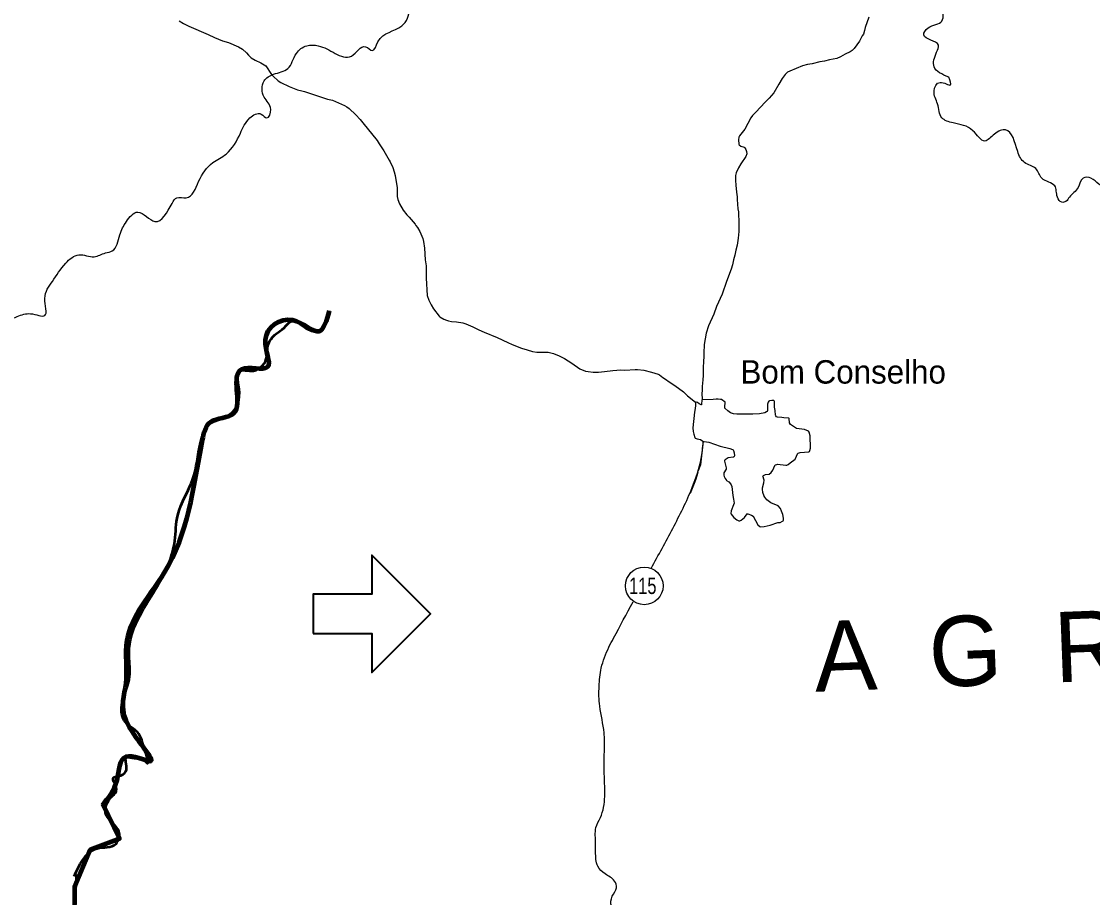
# Model space of a CAD drawing. Extents: x -1643653 to 4543381, y 1624270 to 13878484.
# Drawn here: x 739080 to 761950, y 8976106 to 8994810 of the extents above; entities that cross this region are included whole.
import ezdxf
from ezdxf.enums import TextEntityAlignment as Align

# ---------------------------------------------------------------- set-up
doc = ezdxf.new("R2010")
doc.units = 0
doc.header["$LTSCALE"] = 200
for name, color, linetype, lineweight in [('12', 7, 'Continuous', 25), ('21', 7, 'Continuous', 25), ('24', 7, 'Continuous', 25), ('48', 7, 'Continuous', 25), ('53', 7, 'Continuous', 106), ('60', 7, 'Continuous', 13)]:
    doc.layers.add(name, color=color, linetype=linetype, lineweight=lineweight)
doc.layers.add('41', color=7, linetype='Continuous')
doc.layers.add('55', color=7, linetype='Continuous')

msp = doc.modelspace()

# ---------------------------------------------------------------- linework, layer by layer
at = {"layer": '12'}
for points in [[(757176.2, 8994900.9), (757094.2, 8994681), (757080.3, 8994617.7), (757057.3, 8994539.4), (757030, 8994501.8), (756971.2, 8994387)], [(742450.2, 8994818.9), (742538.4, 8994765.5), (742653.4, 8994708.1), (743063.9, 8994531.9), (743202.8, 8994463.2), (743374.8, 8994394.9), (743503.6, 8994361.7), (743718.4, 8994268.8), (743798, 8994217.1), (743884.6, 8994139.6), (743925.2, 8994087.9), (743987.2, 8994034.5), (744071.1, 8993979.5), (744190.2, 8993923.9), (744295.1, 8993863.4), (744420.2, 8993679.6), (744451.8, 8993640.9), (744562.5, 8993542.9), (744617.5, 8993506.5), (744796.5, 8993422.4), (744976.2, 8993352.4), (745067.8, 8993328), (745127.6, 8993316.5), (745616.2, 8993149), (745683.6, 8993137.9), (745720.2, 8993127.5), (745978.3, 8993014.5), (746031, 8992985.6), (746079.5, 8992950.2), (746223.7, 8992817.6), (746315.6, 8992715.5), (746370.6, 8992646.6)], [(756971.2, 8994387), (756915.9, 8994309.4), (756906.2, 8994289.7), (756893.5, 8994278.5), (756857.7, 8994231), (756816.5, 8994191.4), (756771.9, 8994157.9), (756671.4, 8994111.8), (756570.5, 8994055.5), (756489.1, 8994020.4), (756331.1, 8993988), (756227.8, 8993960.6), (756124.8, 8993944.8), (755962.5, 8993905), (755863.1, 8993888), (755759, 8993864.5), (755485.9, 8993746.7)], [(755485.9, 8993746.7), (755436, 8993725.2), (755388.6, 8993678.9), (755319.8, 8993588), (755254.5, 8993469.5), (755142.1, 8993284), (755043.9, 8993171), (754978.6, 8993106.6), (754841.7, 8992955.8), (754779.1, 8992896.5), (754687.6, 8992799.4), (754651.5, 8992748.6), (754524.1, 8992512.1), (754411.1, 8992365.5), (754398.7, 8992336), (754391.5, 8992281.4), (754397.4, 8992190.1), (754407.1, 8992178.3), (754442.2, 8992150.2), (754510.5, 8992124.1), (754525.7, 8992111.7), (754546.5, 8992078.6), (754558.9, 8992034.2), (754566.8, 8991982.5), (754549.4, 8991924.7), (754437.6, 8991766.5), (754388.2, 8991683.9), (754341.2, 8991577.2), (754329.1, 8991522.1), (754326.6, 8991415.2), (754331, 8991312.1), (754345.5, 8991164.9), (754362.2, 8991061.7), (754363.2, 8991006.3), (754379.5, 8990807.5), (754388.1, 8990748.4), (754401.1, 8990490.5), (754395.5, 8990391.1), (754398.9, 8990324.6), (754386.9, 8990184.8), (754359, 8990030), (754333.6, 8989926.8), (754315.2, 8989820), (754285.7, 8989716.7), (754263.6, 8989613.7), (754232, 8989517.7), (754134.4, 8989256.1), (754043.8, 8988985.6), (753924, 8988727.3), (753924, 8988727.3), (753865.2, 8988561.9), (753752.1, 8988314.6), (753698.9, 8988155), (753660.3, 8987914.5), (753655.8, 8987849.5)], [(755485.9, 8993746.7), (755436, 8993725.2), (755388.6, 8993678.9), (755319.8, 8993588), (755254.5, 8993469.5), (755142.1, 8993284), (755043.9, 8993171), (754978.6, 8993106.6), (754841.7, 8992955.8), (754779.1, 8992896.5), (754687.6, 8992799.4), (754651.5, 8992748.6), (754524.1, 8992512.1), (754411.1, 8992365.5), (754398.7, 8992336), (754391.5, 8992281.4), (754397.4, 8992190.1), (754407.1, 8992178.3), (754442.2, 8992150.2), (754510.5, 8992124.1), (754525.7, 8992111.7), (754546.5, 8992078.6), (754558.9, 8992034.2), (754566.8, 8991982.5), (754549.4, 8991924.7), (754437.6, 8991766.5), (754388.2, 8991683.9), (754341.2, 8991577.2), (754329.1, 8991522.1), (754326.6, 8991415.2), (754331, 8991312.1), (754345.5, 8991164.9), (754362.2, 8991061.7), (754363.2, 8991006.3), (754379.5, 8990807.5), (754388.1, 8990748.4), (754401.1, 8990490.5), (754395.5, 8990391.1), (754398.9, 8990324.6), (754386.9, 8990184.8), (754359, 8990030), (754333.6, 8989926.8), (754315.2, 8989820), (754285.7, 8989716.7), (754263.6, 8989613.7), (754232, 8989517.7), (754134.4, 8989256.1), (754043.8, 8988985.6), (753924, 8988727.3), (753924, 8988727.3), (753865.2, 8988561.9), (753752.1, 8988314.6), (753698.9, 8988155), (753660.3, 8987914.5), (753655.8, 8987849.5)], [(746370.6, 8992646.6), (746675.8, 8992264.3), (746715.6, 8992196.1), (746816.7, 8992049.2), (746928.7, 8991851.2), (746954.4, 8991812.6), (747013.2, 8991690.5), (747042.1, 8991599.5), (747060.7, 8991518.8), (747102.7, 8991255.7), (747100.4, 8991138.7), (747103.3, 8991070.9), (747103.3, 8991070.9), (747120.2, 8991007.4), (747154.3, 8990918), (747231.1, 8990781.3), (747311.3, 8990680), (747360, 8990630), (747445, 8990532.7)], [(747445, 8990532.7), (747489, 8990482.3), (747502.8, 8990454.1), (747534.5, 8990411.4), (747584.5, 8990325.5), (747649, 8990178), (747667.4, 8990112.2), (747687.5, 8989972.1), (747698.6, 8989717.6), (747719, 8989595.1), (747725.2, 8989380.1), (747722.2, 8989329.3), (747746.1, 8988960.3), (747779.8, 8988857.2), (747827.1, 8988762.5), (747875, 8988677.3), (748001.7, 8988515.9), (748016.2, 8988506.6)], [(748016.2, 8988506.6), (748101, 8988452.3), (748156.2, 8988428.9), (748197.1, 8988416.3), (748259.4, 8988404.4), (748370.1, 8988396.3), (748503.1, 8988374.3), (748565.6, 8988354.6), (748721.7, 8988291.5), (748843.5, 8988227.5), (748962.6, 8988172.6), (749234.6, 8988065.8), (749464, 8987954.4), (749561.6, 8987915.9)], [(749561.6, 8987915.9), (749759.4, 8987837.9), (749875.2, 8987797.8), (749994.6, 8987765.6), (750087.1, 8987747.7), (750326.7, 8987747.9), (750386.6, 8987736.9), (750442.4, 8987719.6), (750561.6, 8987669.3), (750673.2, 8987617), (750833.7, 8987517.9), (751003.8, 8987394), (751126.1, 8987342.5), (751181.9, 8987333.4), (751289.8, 8987323.2), (751401.6, 8987324.8), (751529.8, 8987333.9), (751706.3, 8987356.5), (751878.9, 8987368.7), (751963.1, 8987366), (752183.8, 8987382), (752235.9, 8987380.9), (752367.8, 8987368.1), (752532.5, 8987322), (752678, 8987276), (752702.8, 8987264.2), (752772.2, 8987207.5), (752856.2, 8987158.5), (752892, 8987129.4), (753033.4, 8987040.5), (753213, 8986899.7), (753304.7, 8986813.7), (753474.8, 8986678.9)], [(753655.8, 8987849.5), (753652, 8987794.5), (753649.1, 8987635.6), (753642.4, 8987573.9), (753636.8, 8987402.8), (753638.3, 8987253.7), (753631.8, 8987159.1), (753615.3, 8987017.2), (753614.7, 8986926.3), (753609, 8986874.3), (753612.6, 8986736)], [(753655.8, 8987849.5), (753652, 8987794.5), (753649.1, 8987635.6), (753642.4, 8987573.9), (753636.8, 8987402.8), (753638.3, 8987253.7), (753631.8, 8987159.1), (753615.3, 8987017.2), (753614.7, 8986926.3), (753609, 8986874.3), (753612.6, 8986736)], [(753633, 8985850), (753576.7, 8985344), (753530.3, 8985214.1)], [(753519, 8985182.5), (753479.2, 8985039.8), (753458.8, 8984981.2), (753358.6, 8984732.6)]]:
    msp.add_lwpolyline(points, dxfattribs=at)
for points in [[(752526, 8983133.9), (752986.9, 8983987.8), (753403.6, 8984862), (753591.8, 8985477.9), (753638.8, 8985834.3)], [(752444.7, 8974591.9), (752220.7, 8974690.3), (751998.9, 8974824.7), (751911.5, 8975012.9), (751817.4, 8975268.3), (751824.1, 8975476.7), (751783.8, 8975691.7), (751676.2, 8975920.3), (751696.4, 8976135.3), (751783.8, 8976316.8), (751743.5, 8976458), (751541.8, 8976612.5), (751387.2, 8976773.8), (751340.2, 8977083), (751333.5, 8977432.5), (751346.9, 8977600.6), (751441, 8977812.6), (751535.1, 8978263.1), (751521.7, 8978828), (751528.4, 8979271.8), (751521.7, 8979621.5), (751427.6, 8980193.1), (751414.1, 8980616.7), (751461.2, 8981006.8), (751622.5, 8981450.6), (751723.3, 8981645.6), (752140.5, 8982419.4)]]:
    msp.add_spline(points, degree=3, dxfattribs=at)
at = {"layer": '21'}
for points in [[(754106.5, 8986680.5), (754028.4, 8986735.9), (754008.6, 8986741.8), (753959.7, 8986746.4), (753911.5, 8986745.8), (753847.3, 8986736.2), (753617.4, 8986734.1), (753610.5, 8986721), (753603, 8986636.5), (753598.5, 8986625.7), (753593.3, 8986622.8), (753548.2, 8986646.6), (753513.2, 8986676.1), (753489.4, 8986684.9), (753479.3, 8986681.3), (753473.2, 8986665.5), (753471.1, 8986603.5), (753456.9, 8986505.7)], [(755463.7, 8986343), (755359.2, 8986349), (755313.3, 8986357.6), (755225.2, 8986360), (755200.7, 8986372.1), (755184.6, 8986391.3), (755179.9, 8986406.1), (755172.6, 8986505.7), (755160.5, 8986575.6), (755157.9, 8986696.6), (755154.6, 8986709), (755144.5, 8986717.7), (755099.3, 8986716.4), (755051.6, 8986708.7), (755037.8, 8986701.8), (755021.5, 8986685), (755006.7, 8986638.5), (755009.5, 8986566), (755006.7, 8986501), (755001.5, 8986483.7), (754990.6, 8986472.3), (754949.5, 8986450.8), (754835.7, 8986433), (754694, 8986426.1), (754358.5, 8986424.1), (754285.6, 8986433.3), (754221.1, 8986453.4), (754162.9, 8986497.5), (754099.2, 8986557.1), (754095.9, 8986575.3), (754106.5, 8986680.5)], [(753456.9, 8986505.7), (753451.7, 8986470.4), (753417.7, 8986131.5), (753423.5, 8986054.9), (753436.8, 8985998.3), (753459.2, 8985928.4), (753468.7, 8985916.1), (753504.7, 8985896.3), (753581.4, 8985882.6), (753631.7, 8985851.6), (753656, 8985840.8), (753753.8, 8985828.2), (754001.5, 8985739.7), (754207.2, 8985690), (754265.7, 8985669.4), (754278, 8985661.9), (754285, 8985652.1), (754300.8, 8985600.5), (754303.9, 8985539.2), (754296.8, 8985521.3), (754284.9, 8985509.2), (754274.8, 8985505.2), (754168.7, 8985495.8), (754105.6, 8985448.6), (754092.8, 8985434.4), (754092.1, 8985422.4), (754127.9, 8985277.1), (754124.1, 8985252.2), (754079.9, 8985172.5), (754077, 8985121), (754081, 8985097.3), (754105.4, 8985051.6), (754127.7, 8985027.4), (754137.5, 8985008), (754181.1, 8984978.6), (754227.8, 8984934.9), (754247.5, 8984880.2), (754270.2, 8984687.2), (754283.8, 8984614.6), (754295.2, 8984523.1), (754286.3, 8984492.2), (754235.9, 8984364.6), (754229.1, 8984308.5), (754236.8, 8984288.9), (754289.6, 8984223.1), (754353.6, 8984172.3), (754396.8, 8984149.9), (754417.7, 8984147.5), (754444.8, 8984159.8), (754522, 8984218.2), (754577.1, 8984295.8), (754587.6, 8984296.2), (754671, 8984266.2), (754701.7, 8984245.3), (754806.1, 8984064), (754848, 8984027.6), (754866.2, 8984018.8), (754939.3, 8984028), (755065.3, 8984056.9), (755228.7, 8984110.9), (755278.6, 8984115.5), (755332.8, 8984138), (755345.8, 8984148.7), (755349.7, 8984161.8), (755350.8, 8984206.2), (755335.7, 8984282.9), (755311.7, 8984351.5), (755283.8, 8984415.4), (755236.2, 8984470.9), (755082.2, 8984529.5), (755020.7, 8984572.5), (754993.5, 8984596.2), (754950, 8984652.2), (754938.2, 8984672.7), (754911.7, 8984751.8), (754902.8, 8984821.5), (754904.4, 8984856.5), (754929.6, 8984958.3), (754935.6, 8985018.6), (754933.4, 8985034.7), (754913.9, 8985089.7), (754913.2, 8985105.4), (754922.8, 8985115.9), (754969.6, 8985136.5), (755045.1, 8985148.2), (755045.1, 8985148.2), (755089.7, 8985177.8), (755121.3, 8985227.3), (755167.3, 8985327.7), (755182.7, 8985345.9), (755206, 8985350), (755225, 8985358.8), (755398.6, 8985334.3), (755419.4, 8985337.3), (755454.3, 8985352.7), (755491.7, 8985386.9), (755598.4, 8985464.8), (755610.1, 8985482.6), (755653.5, 8985579.7), (755666.6, 8985594.3), (755707, 8985610.9)], [(755707, 8985610.9), (755890.2, 8985621.7), (755905.4, 8985627.2), (755915.8, 8985647.5), (755925.1, 8985701.8), (755922.8, 8985964.8), (755902.2, 8986043.6), (755886.2, 8986060.2), (755799.9, 8986101.9), (755630.8, 8986122.8), (755520.9, 8986187.7), (755503.2, 8986203.3), (755475.9, 8986240.2), (755469.1, 8986332.7), (755463.7, 8986343), (755463.7, 8986343)]]:
    msp.add_lwpolyline(points, dxfattribs=at)
at = {"layer": '21', "lineweight": 13}
for points in [[(753456.9, 8986505.7), (753451.7, 8986470.4), (753417.7, 8986131.5), (753423.5, 8986054.9), (753436.8, 8985998.3), (753459.2, 8985928.4), (753468.7, 8985916.1), (753504.7, 8985896.3), (753581.4, 8985882.6), (753631.7, 8985851.6), (753656, 8985840.8), (753753.8, 8985828.2), (754001.5, 8985739.7), (754207.2, 8985690), (754265.7, 8985669.4), (754278, 8985661.9), (754285, 8985652.1), (754300.8, 8985600.5), (754303.9, 8985539.2), (754296.8, 8985521.3), (754284.9, 8985509.2), (754274.8, 8985505.2), (754168.7, 8985495.8), (754105.6, 8985448.6), (754092.8, 8985434.4), (754092.1, 8985422.4), (754127.9, 8985277.1), (754124.1, 8985252.2), (754079.9, 8985172.5), (754077, 8985121), (754081, 8985097.3), (754105.4, 8985051.6), (754127.7, 8985027.4), (754137.5, 8985008), (754181.1, 8984978.6), (754227.8, 8984934.9), (754247.5, 8984880.2), (754270.2, 8984687.2), (754283.8, 8984614.6), (754295.2, 8984523.1), (754286.3, 8984492.2), (754235.9, 8984364.6), (754229.1, 8984308.5), (754236.8, 8984288.9), (754289.6, 8984223.1), (754353.6, 8984172.3), (754396.8, 8984149.9), (754417.7, 8984147.5), (754444.8, 8984159.8), (754522, 8984218.2), (754577.1, 8984295.8), (754587.6, 8984296.2), (754671, 8984266.2), (754701.7, 8984245.3), (754806.1, 8984064), (754848, 8984027.6), (754866.2, 8984018.8), (754939.3, 8984028), (755065.3, 8984056.9), (755228.7, 8984110.9), (755278.6, 8984115.5), (755332.8, 8984138), (755345.8, 8984148.7), (755349.7, 8984161.8), (755350.8, 8984206.2), (755335.7, 8984282.9), (755311.7, 8984351.5), (755283.8, 8984415.4), (755236.2, 8984470.9), (755082.2, 8984529.5), (755020.7, 8984572.5), (754993.5, 8984596.2), (754950, 8984652.2), (754938.2, 8984672.7), (754911.7, 8984751.8), (754902.8, 8984821.5), (754904.4, 8984856.5), (754929.6, 8984958.3), (754935.6, 8985018.6), (754933.4, 8985034.7), (754913.9, 8985089.7), (754913.2, 8985105.4), (754922.8, 8985115.9), (754969.6, 8985136.5), (755045.1, 8985148.2), (755045.1, 8985148.2), (755089.7, 8985177.8), (755121.3, 8985227.3), (755167.3, 8985327.7), (755182.7, 8985345.9), (755206, 8985350), (755225, 8985358.8), (755398.6, 8985334.3), (755419.4, 8985337.3), (755454.3, 8985352.7), (755491.7, 8985386.9), (755598.4, 8985464.8), (755610.1, 8985482.6), (755653.5, 8985579.7), (755666.6, 8985594.3), (755707, 8985610.9)], [(755707, 8985610.9), (755890.2, 8985621.7), (755905.4, 8985627.2), (755915.8, 8985647.5), (755925.1, 8985701.8), (755922.8, 8985964.8), (755902.2, 8986043.6), (755886.2, 8986060.2), (755799.9, 8986101.9), (755630.8, 8986122.8), (755520.9, 8986187.7), (755503.2, 8986203.3), (755475.9, 8986240.2), (755469.1, 8986332.7), (755463.7, 8986343), (755463.7, 8986343)]]:
    msp.add_lwpolyline(points, dxfattribs=at)
at = {"layer": '24', "lineweight": 53}
msp.add_lwpolyline([(740256.1, 8976602), (740150, 8974957.6), (740199.7, 8974820.8)], dxfattribs=at)
at = {"layer": '24'}
for points in [[(758879.2, 8993619.3), (758566.2, 8993840.3), (758621.5, 8994153.5), (758658.3, 8994300.8), (758345.4, 8994521.8), (758437.4, 8994669.2), (758731.9, 8994816.6), (758750.3, 8995184.9), (758787.1, 8995406), (758731.9, 8995645.4), (758842.3, 8995903.3), (758842.3, 8996069), (758658.3, 8996087.5), (758511, 8995866.4), (758327, 8995884.8), (758253.3, 8996087.5), (758087.7, 8996179.5), (758069.2, 8995958.5), (757977.2, 8995903.3), (757811.6, 8996087.5), (757811.6, 8996363.7), (757811.6, 8996492.7), (757682.7, 8996584.8), (757314.6, 8996658.4), (757259.3, 8996842.6), (757259.3, 8997026.8), (757038.5, 8997303.1), (756983.2, 8997542.5), (757167.3, 8997855.7), (757130.5, 8998187.2), (757001.6, 8998371.4), (757112.1, 8998702.9), (757222.5, 8998942.4), (757056.9, 8999181.8), (757056.9, 8999384.4), (756854.4, 8999476.5), (756836, 8999789.6), (757001.6, 8999955.4), (757093.7, 9000231.7), (757222.5, 9000581.7), (757425, 9000729), (757572.3, 9000968.5), (757719.5, 9000968.5), (757737.9, 9001171.1), (757682.7, 9001484.2), (757811.6, 9001668.4), (757866.8, 9001981.5), (758050.8, 9002313), (758290.1, 9002405.1), (758474.2, 9002294.6), (758676.7, 9002478.8), (759044.8, 9003105), (759192.1, 9003123.5), (759339.3, 9003289.2), (759541.8, 9003436.6)], [(733215.8, 8989848.5), (733722.5, 8989807.9), (733844.1, 8989807.9), (733965.7, 8989889), (734168.3, 8989909.3), (734431.8, 8989970.2), (734634.5, 8989868.8), (734898, 8989524), (735100.6, 8989361.8), (735404.6, 8989402.3), (735668.1, 8989280.6), (735911.3, 8989037.3), (735931.6, 8988895.3), (736073.4, 8988935.9), (736276.1, 8989017), (736499, 8988854.8), (736478.8, 8988510), (736600.4, 8988408.6), (736478.8, 8988307.2), (736418, 8988226.1), (736600.4, 8988084.1), (736823.3, 8987556.8), (736985.5, 8987394.6), (737046.2, 8987333.8), (737269.2, 8987374.3), (737431.3, 8987475.7), (737897.5, 8987658.2), (738181.2, 8987861), (738465, 8988043.6), (738647.3, 8988043.6), (738687.9, 8988286.9), (738991.9, 8988510), (739275.6, 8988570.8), (739579.6, 8988530.3), (739579.6, 8988895.3), (739741.8, 8989260.4), (740025.5, 8989645.7), (740309.2, 8989828.2), (740633.5, 8989787.6), (740876.7, 8989868.8), (741018.6, 8989909.3), (741180.7, 8990254.1), (741322.6, 8990538), (741565.8, 8990740.8), (741930.6, 8990538), (742295.4, 8990923.3), (742396.8, 8991045), (742599.4, 8991045), (742862.9, 8991389.8), (743166.9, 8991795.3), (743450.7, 8991977.9), (743754.7, 8992424), (743957.3, 8992748.5), (744200.5, 8992829.6), (744322.1, 8992748.5), (744403.2, 8992931), (744261.3, 8993194.7), (744261.3, 8993539.4), (744464, 8993681.4), (744768, 8993803.1), (744950.4, 8994127.6), (745173.3, 8994289.8), (745416.6, 8994289.8), (745781.4, 8994127.6), (746125.9, 8994066.7), (746429.9, 8994269.5), (746571.8, 8994188.4), (746693.4, 8994370.9), (747200.1, 8994715.7), (747341.9, 8995080.7), (747281.1, 8995283.5), (747524.3, 8995405.2), (747585.1, 8995466), (747483.8, 8995587.7), (747463.5, 8995831.1), (747585.1, 8995912.2), (747585.1, 8996115), (747666.2, 8996358.3), (747868.9, 8996561.1), (747970.2, 8996642.3), (747949.9, 8997047.9), (748152.6, 8997068.1), (748152.6, 8997291.2), (748456.6, 8997656.3), (748720.1, 8997656.3), (748882.2, 8997737.4), (748882.2, 8998102.4), (749125.4, 8998264.7), (749307.8, 8998264.7), (749368.6, 8998264.7), (749307.8, 8998508)], [(771983.6, 8980431.6), (771458.1, 8980369.7), (771148.9, 8980648.1), (771087.1, 8980988.4), (770932.5, 8981297.7), (770808.9, 8981638), (770345.2, 8981761.8), (770005.1, 8981885.5), (769819.6, 8982071.1), (769634.1, 8981854.6), (769479.5, 8982009.2), (769015.8, 8982318.6), (768923.1, 8982689.8), (768706.7, 8982937.2), (768593.5, 8983157.4), (768713.2, 8983415.3), (768842, 8983516.6), (768842, 8983590.2), (768630.3, 8983700.8), (768289.8, 8983940.2), (768207, 8984262.5), (768022.9, 8984465.2), (767700.8, 8984557.2), (767590.3, 8984640.1), (767553.5, 8985036.1), (767599.5, 8985266.4), (767599.5, 8985422.9), (767461.5, 8985607.1), (767314.2, 8985634.8), (767268.2, 8985533.4), (767139.4, 8985496.6), (766918.5, 8985616.3), (766789.6, 8985818.9), (766559.5, 8985957.1), (766219, 8986297.8), (765850.9, 8986500.4), (765363.1, 8986924.1), (764801.7, 8987504.3), (764663.6, 8987624), (764378.3, 8988066), (764295.5, 8988259.4), (764221.8, 8988296.3), (764083.8, 8988204.2), (763982.5, 8988268.6), (763669.6, 8988664.7), (763586.8, 8988683.1), (763540.8, 8988848.8), (763605.2, 8988913.3), (763665, 8988922.5), (763720.2, 8989088.3), (763554.6, 8989254.1), (763480.9, 8989475.1), (763628.2, 8989677.7), (763977.9, 8989935.6), (764143.6, 8990101.3), (764125.2, 8990285.5), (763849.1, 8990377.6), (763793.9, 8990525), (763591.4, 8990617.1), (763480.9, 8990635.5), (763260.1, 8990525), (763094.4, 8990525), (762965.5, 8990635.5), (762818.3, 8990856.5), (762781.5, 8990930.2), (762652.6, 8990967), (762450.1, 8991169.6), (762082, 8991335.4), (761916.3, 8991464.3), (761750.7, 8991464.3), (761640.2, 8991261.7), (761456.2, 8991059.1), (761382.5, 8990967), (761290.5, 8990948.6), (761198.5, 8991059.1), (761143.2, 8991298.6), (760867.1, 8991464.3), (760738.3, 8991666.9), (760499, 8991795.9), (760351.7, 8992035.3), (760094, 8992495.8), (759854.7, 8992403.7), (759652.3, 8992256.3), (759394.6, 8992477.3), (758971.2, 8992643.1), (758731.9, 8992753.6), (758639.9, 8993048.3), (758566.2, 8993324.6), (758695.1, 8993508.8), (758916, 8993453.6), (758879.2, 8993619.3)]]:
    msp.add_spline(points, degree=3, dxfattribs=at)
at = {"layer": '24', "lineweight": 53}
msp.add_spline([(740207.8, 8976565.1), (740390.3, 8976909.9), (740694.3, 8977153.2), (741099.6, 8977254.6), (741160.4, 8977518.3), (741038.8, 8977680.5), (740876.7, 8977923.9), (740998.3, 8978248.3), (741099.6, 8978370), (741099.6, 8978471.4), (741038.8, 8978653.9), (741200.9, 8978714.8), (741322.5, 8978836.5), (741322.5, 8979100.1), (741484.7, 8979079.8), (741646.8, 8979079.8), (741768.4, 8978978.4), (741707.6, 8979282.6), (741525.2, 8979667.9), (741302.3, 8979850.5), (741221.2, 8980215.5), (741383.3, 8980763.1), (741383.3, 8981209.2), (741383.3, 8981432.3), (741991.3, 8982770.8), (742356.2, 8983723.9), (742417, 8984271.5), (742741.2, 8985042.1), (742903.4, 8985812.8), (743106, 8986218.4), (743470.8, 8986380.6), (743734.3, 8986887.6), (743734.3, 8987354.1), (744038.3, 8987354.1), (744322.1, 8987658.2), (744342.3, 8987881.3), (744524.7, 8988145), (744686.9, 8988266.7), (744849, 8988408.6), (745031.4, 8988347.8), (745274.6, 8988205.8), (745416.5, 8988205.8), (745598.9, 8988388.3), (745659.7, 8988631.7)], degree=3, dxfattribs=at)
at = {"layer": '48'}
msp.add_circle((752378.4, 8982760.1), 401.3, dxfattribs=at)
at = {"layer": '53', "lineweight": 35}
msp.add_lwpolyline([(745311.6, 8981746.7), (746561.6, 8981746.7), (746561.6, 8980913.5), (747811.6, 8982163.5), (746561.6, 8983413.5), (746561.6, 8982580.2), (745311.6, 8982580.2)], close=True, dxfattribs=at)
at = {"layer": '53'}
msp.add_lwpolyline([(740811.1, 8978107.8), (741171, 8977363.2), (740547.2, 8977123), (740211.3, 8976330.4), (740199.7, 8974820.8)], dxfattribs=at)
msp.add_spline([(740811.1, 8978083.8), (741123, 8978612.2), (741314.9, 8979116.5), (741818.7, 8979020.5), (741314.9, 8979885.1), (741314.9, 8980677.7), (741338.7, 8981597.5), (742130.4, 8983038.5), (742946.1, 8985872.7), (743114, 8986257), (743617.8, 8986449.1), (743785.8, 8987385.8), (744337.6, 8987433.8), (744289.6, 8988010.3), (744865.3, 8988437.8), (745441.1, 8988197.6), (745657, 8988629.9)], degree=3, dxfattribs=at)
at = {"layer": '60', "lineweight": 25}
msp.add_spline([(814781, 9009175.5), (814787.2, 9009173.4), (814796.9, 9009173.4), (814799.4, 9009172.4), (814805.1, 9009174.5), (814805.6, 9009176.5), (814811.7, 9009179.5), (814811.7, 9009179.5), (814801.5, 9009181), (814790.7, 9009181.5), (814784.1, 9009183.1), (814777.4, 9009185.1), (814778.4, 9009175.5)], degree=3, dxfattribs=at)

# ---------------------------------------------------------------- texts
at = {"layer": '41'}
msp.add_text('Bom Conselho', height=500, dxfattribs=at).set_placement((754433.5, 8987078.3))
at = {"layer": '48', "width": 0.75}
msp.add_text('115', height=350, dxfattribs=at).set_placement((752346.8, 8982586.7), align=Align.CENTER)
at = {"layer": '55'}
msp.add_text('A  G  R  E  S  T  E', height=1500, rotation=2.229, dxfattribs=at).set_placement((756032.3, 8980498.3))

doc.saveas('drawing.dxf')
